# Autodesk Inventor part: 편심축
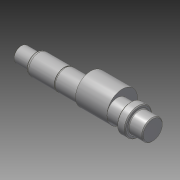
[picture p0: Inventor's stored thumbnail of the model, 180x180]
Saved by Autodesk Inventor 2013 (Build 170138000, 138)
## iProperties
Created: 2023-03
Part Number: 편심축
Material: 강철, 연강
Document SubType Name: Modeling
Designer: mdu-01
Density: 1 g/cm^3
Author: mdu-01
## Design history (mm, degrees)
sketch "스케치1"
  geometry: L1 (0, 0)-(160, 0); L2 (160, 0)-(160, 11.5); L3 (159, 12.5)-(144, 12.5); L4 (143, 13.5)-(143, 16.5); L5 (143, 16.5)-(133, 16.5); L6 (133, 16.5)-(133, 12.5); L7 (19, 10.961)-(19, 9); L8 (19, 9)-(1, 9); L9 (0, 8)-(0, 0); L10 (79, 12.5)-(79, 0); L11 (117, 12.5)-(117, 0); L12 (160, 11.5)-(159, 12.5); L13 (54.35, 12.5)-(54.35, 11.95); L14 (54.35, 11.95)-(53, 11.95); L15 (53, 11.95)-(53, 12.5); L16 (133, 12.5)-(54.35, 12.5); L17 (53, 12.5)-(22.237, 12.5); L18 (19.25, 11.394)-(20.237, 11.964); L19 (1, 9)-(0, 8); L20 (3, 5.5)-(17, 5.5); L21 (3, 5.5)-(3, 9); L22 (17, 5.5)-(17, 9); A1 r 1 centre (144, 13.5) between (143, 13.5) and (144, 12.5); A2 r 0.5 centre (19.5, 10.961) between (19.25, 11.394) and (19, 10.961); A3 r 4 centre (22.237, 8.5) between (22.237, 12.5) and (20.237, 11.964); 3 further points
  constraints: 44 end point, 12 perpendicular, 12 point on line, 10 parallel, 6 point on circle, 6 tangent, 3 centre point, 2 collinear, 1 horizontal
  dimensions: "d0" = 18 diameter of L8 L1; "d2" = 38 distance between parallel lines of L11 L10; "d3" = 16 distance between parallel lines of L6 L11; "d4" = 25 diameter of L3 L1; "d5" = 17 distance between parallel lines of L2 L4; "d6" = 1 distance of L2.end point (160, 12.5); "d7" = 1 distance of L3.start point (160, 12.5) (= d6); "d8" = 10 distance between parallel lines of L4 L6; "d9" = 33 diameter of L5 L1; "d10" = 1 radius of A1; "d11" = 23.9 diameter of L14 L1; "d12" = 1.35 distance between parallel lines of L13 L15; "d13" = 26 distance between parallel lines of L15 L10; "d14" = 34 distance between parallel lines of L7 L15; "d15" = 19 distance between parallel lines of L9 L7; "d16" = 22.5 diameter of point (19, 11.25) L1; "d17" = 30 deg angle of L18 L17; "d18" = 0.5 radius of A2; "d19" = 1.96132 distance of L7.start L7.end (derived); "d20" = 4 radius of A3; "d21" = 1 distance of L8.end point (0, 9); "d22" = 1 distance of L9.start point (0, 9) (= d21); "d24" = 3.5 distance between parallel lines of L20 L8; "d25" = 14 distance between parallel lines of L22 L21; "d26" = 2 distance between parallel lines of L7 L22; "d45" = 160 distance between parallel lines of L2 L9 (derived)
revolve "회전1" stored, may be unused: angle "d23" = 90 deg
extrude "돌출1" cut sketch "스케치1" stored distance "d27" = 6; taper "d28" = 0 deg
fillet "모깎기1"
fillet "모깎기2"
hole "구멍1" diameter "d31" = 6.647; stored, may be unused: countersink angle "d35" = 90 deg, drill point angle "d37" = 118 deg; dims "d32" = 16, "d33" = 4, "d34" = 2, "d36" = 18, "d48" = 10, "d49" = 10
sketch "스케치2"
  geometry: L1 (79, 6)-(117, 6); L2 (117, 12.5)-(117, 0) reference; L3 (79, 12.5)-(79, 0) reference; L4 (79, 6)-(79, -12.5); L5 (79, -12.5)-(117, -12.5); L6 (117, -12.5)-(117, 6); 1 further point
  constraints: 8 end point, 3 perpendicular, 2 collinear, 2 point on line, 1 horizontal
  dimensions: "d39" = 6 distance from line of point (0, 0) L1; "d40" = 12.5 distance from line of L5 point (0, 0)
revolve "회전2" sketch "스케치2" stored, may be unused: angle "d41" = 90 deg
chamfer "모따기1" distance "d42" = 1; stored, may be unused: second distance "d43" = 2, angle "d44" = 45 deg
node "솔리드1"
